// Mitsubishi GX Works2 project: 11.延时启动延时停止   PLC: FX3U/FX3UC

PROGRAM MAIN
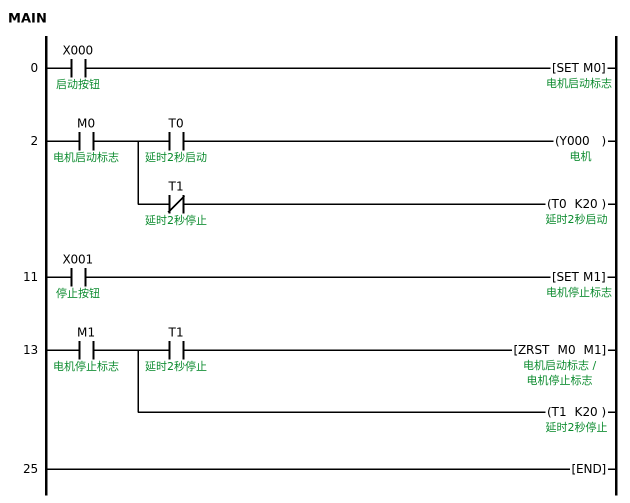
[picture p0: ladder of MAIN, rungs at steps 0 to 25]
0     LD      X000  ; 启动按钮
      SET     M0  ; 电机启动标志
2     LD      M0  ; 电机启动标志
      MPS
      AND     T0  ; 延时2秒启动
      OUT     Y000  ; 电机
      MPP
      ANI     T1  ; 延时2秒停止
      OUT     T0 K20  ; 延时2秒启动
11    LD      X001  ; 停止按钮
      SET     M1  ; 电机停止标志
13    LD      M1  ; 电机停止标志
      MPS
      AND     T1  ; 延时2秒停止
      ZRST    M0 M1
      MPP
      OUT     T1 K20  ; 延时2秒停止
25    END
END_PROGRAM
